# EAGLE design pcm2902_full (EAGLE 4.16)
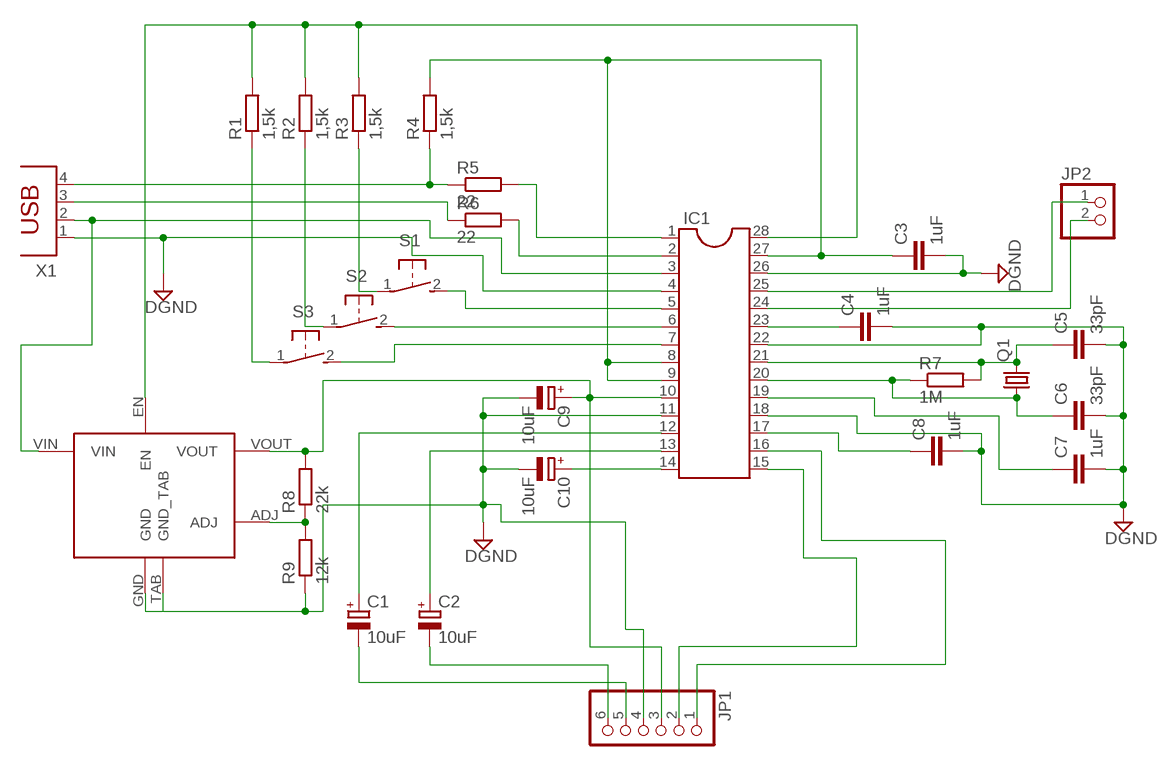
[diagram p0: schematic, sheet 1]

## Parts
C1  10uF  CPOL-EUE2.5-5  [E2,5-5]
C2  10uF  CPOL-EUE2.5-5  [E2,5-5]
C3  1uF  C-EU050-024X044  [C050-024X044]
C4  1uF  C-EU050-024X044  [C050-024X044]
C5  33pF  C-EU050-024X044  [C050-024X044]
C6  33pF  C-EU050-024X044  [C050-024X044]
C7  1uF  C-EU050-024X044  [C050-024X044]
C8  1uF  C-EU050-024X044  [C050-024X044]
C9  10uF  CPOL-EUE2.5-5  [E2,5-5]
C10  10uF  CPOL-EUE2.5-5  [E2,5-5]
IC1  DIL28  [DIL28-6]
JP1  PINHD-1X6  [1X06]
JP2  PINHD-1X2  [1X02]
Q1  CRYTALHC49S  [HC49/S]
R1  1,5k  R-EU_0204/7  [0204/7]
R2  1,5k  R-EU_0204/7  [0204/7]
R3  1,5k  R-EU_0204/7  [0204/7]
R4  1,5k  R-EU_0204/7  [0204/7]
R5  22  R-EU_0204/7  [0204/7]
R6  22  R-EU_0204/7  [0204/7]
R7  1M  R-EU_0204/5  [0204/5]
R8  22k  R-EU_0204/5  [0204/5]
R9  12k  R-EU_0204/5  [0204/5]
S1  31-XX  [B3F-31XX]
S2  31-XX  [B3F-31XX]
S3  31-XX  [B3F-31XX]
U$1  REG102GA-A  [SOT223-5]
X1  PN87520  [PN87520]

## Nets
D_OUT: IC1.25 JP2.1
DGND: C3.2 C4.2 C5.2 C6.2 C7.2 C8.2 C9.- C10.- IC1.4 IC1.11 IC1.18 IC1.22 IC1.26 JP1.4 R9.1 U$1.GND U$1.TAB(GND_TAB) X1.1
N$1: C10.+ IC1.14
N$2: C9.+ IC1.10 JP1.3 R8.2 U$1.VOUT
N$3: IC1.1 R5.2
N$4: R4.1 R5.1 X1.4
N$5: R6.1 X1.3
N$6: IC1.2 R6.2
N$7: IC1.6 S2.2(S)
N$8: C3.1 IC1.8 IC1.9 IC1.27 R4.2
N$9: IC1.7 S3.2(S)
N$10: IC1.5 S1.2(S)
N$11: R1.1 S3.1(P)
N$12: R2.1 S2.1(P)
N$13: R3.1 S1.1(P)
N$14: C4.1 IC1.23
N$15: IC1.28 R1.2 R2.2 R3.2 U$1.EN
N$16: C1.+ IC1.12
N$17: C2.+ IC1.13
N$18: C5.1 IC1.21 Q1.2 R7.2
N$19: C6.1 IC1.20 Q1.1 R7.1
N$20: C7.1 IC1.19
N$21: C8.1 IC1.17
N$22: IC1.16 JP1.1
N$23: IC1.24 JP2.2
N$26: IC1.3 U$1.VIN X1.2
N$27: IC1.15 JP1.2
N$28: C1.- JP1.5
N$29: C2.- JP1.6
N$32: R8.1 R9.2 U$1.ADJ

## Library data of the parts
C1 C2 C9 C10 = rcl:CPOL-EU: POLARIZED CAPACITOR, European symbol
C3-C8 = rcl:C-EU: CAPACITOR, European symbol
IC1 = ic-package:DIL28: Dual In Line
JP1 = pinhead:PINHD-1X6: PIN HEADER
JP2 = pinhead:PINHD-1X2: PIN HEADER
Q1 = crystal:CRYTAL: CRYSTAL
R1-R9 = rcl:R-EU_: RESISTOR, European symbol
S1-S3 = switch-omron:31-XX: OMRON SWITCH
U$1 = Reg102:REG102GA-A
X1 = con-berg:PN87520: BERG USB connector

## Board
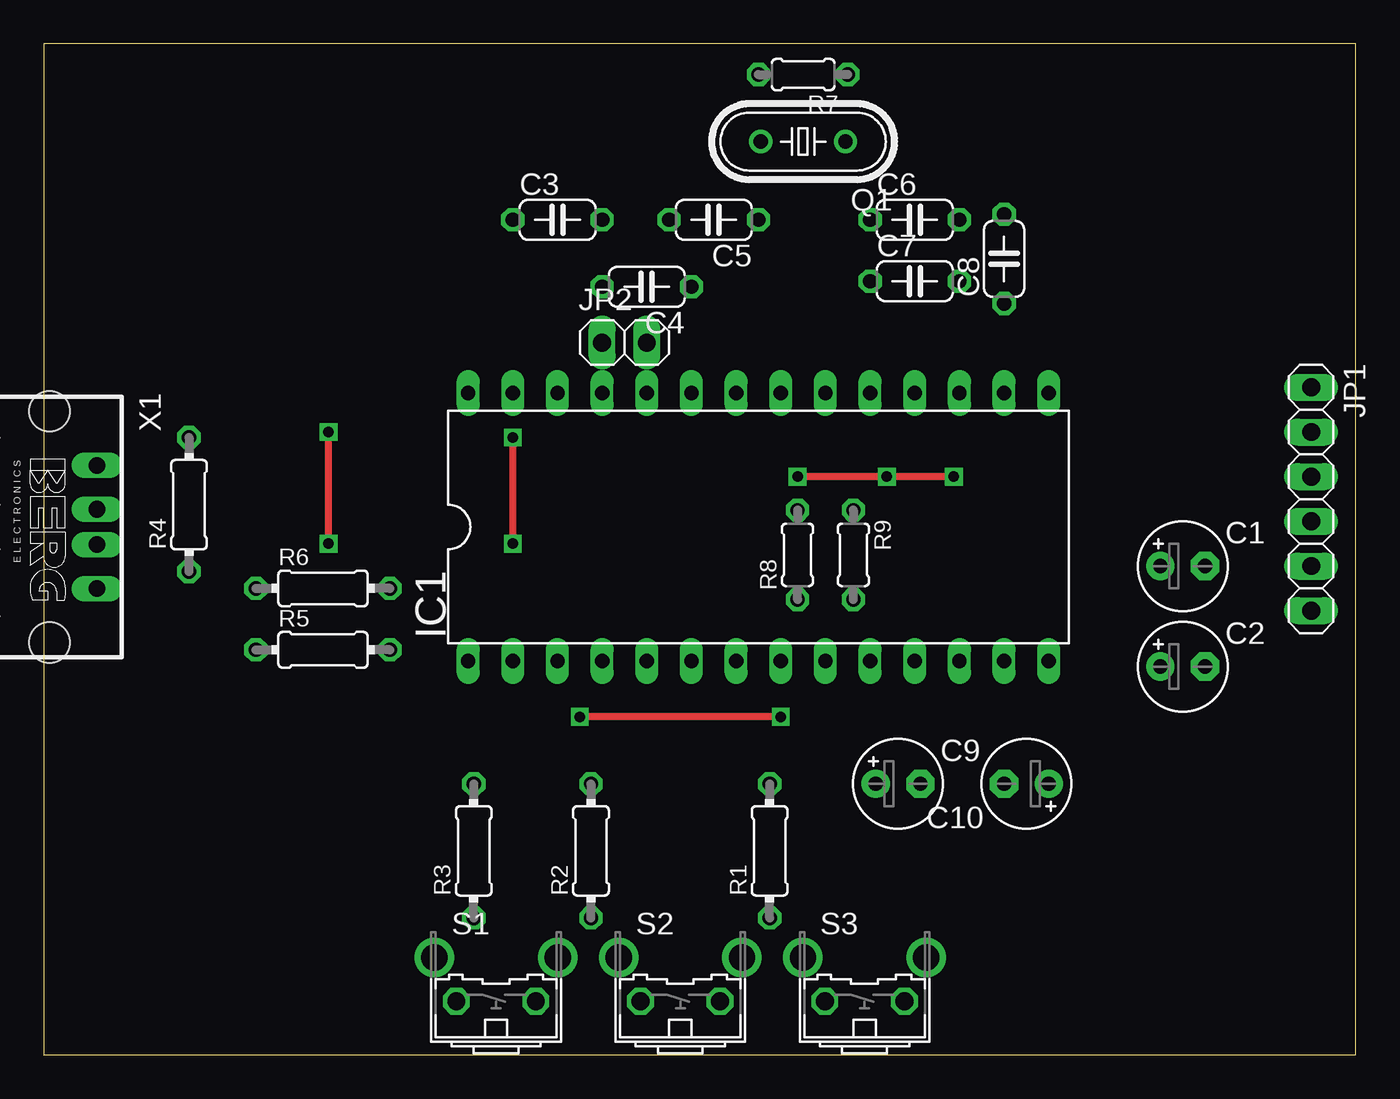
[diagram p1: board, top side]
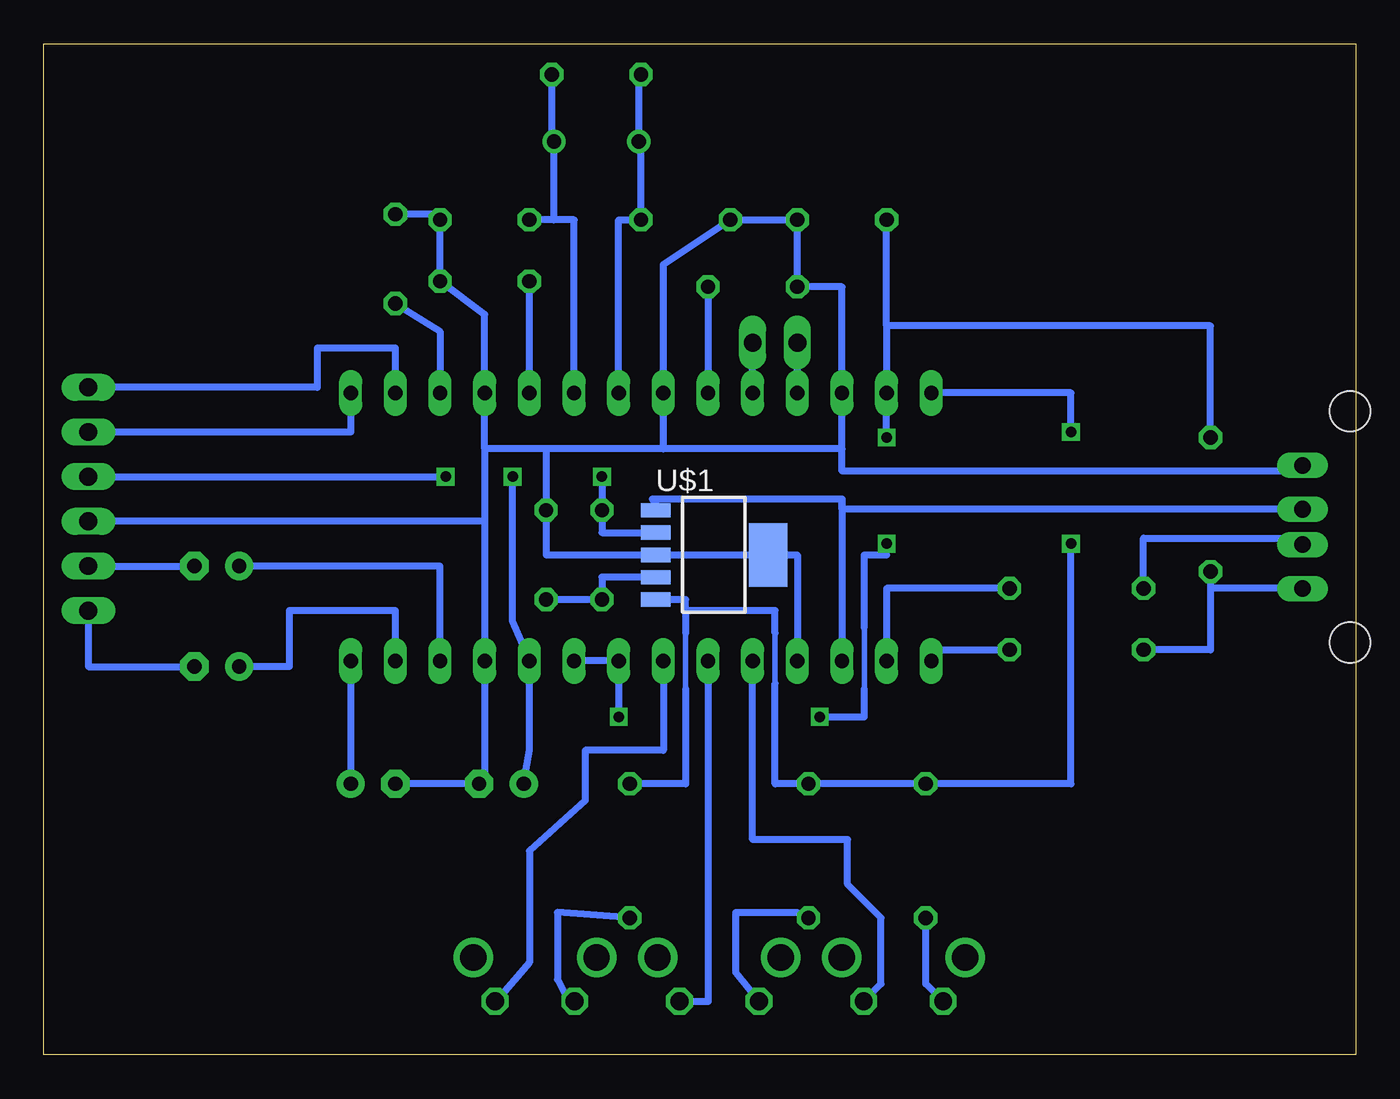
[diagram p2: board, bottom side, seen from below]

Size 74.59 x 57.45 mm. Coordinates in mm from the lower left corner, seen from the top.
Outline: 0,0 74.59,0 74.59,57.45 0,57.45 0,0
Copper layers (1*16): Top 0.035mm / dielectric 1.5mm / Bottom 0.035mm
Design rules "default": minimum track width 10mil, minimum drill 24mil, track to track 8mil, track to pad 8mil, pad to pad 8mil, via to via 8mil, smd to smd 8mil, copper to edge 40mil, drill to drill 8mil, minimum pad ring 10mil, minimum via ring 8mil, stop-mask expansion 4mil, vias tented up to drill 0mil, thermal gap 10mil

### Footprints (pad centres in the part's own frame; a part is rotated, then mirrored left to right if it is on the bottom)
E2,5-5 = drill 0.813 pad 1.6 round: + -1.27,0 | drill 0.813 pad 1.6 octagon: - 1.27,0
C050-024X044 = drill 0.813 octagon: 1 -2.54,0; 2 2.54,0
DIL28-6 = drill 0.813 long: 1 -16.51,-7.62; 2 -13.97,-7.62; 3 -11.43,-7.62; 4 -8.89,-7.62; 5 -6.35,-7.62; 6 -3.81,-7.62; 7 -1.27,-7.62; 8 1.27,-7.62; 9 3.81,-7.62; 10 6.35,-7.62; 11 8.89,-7.62; 12 11.43,-7.62; 13 13.97,-7.62; 14 16.51,-7.62; 15 16.51,7.62; 16 13.97,7.62; 17 11.43,7.62; 18 8.89,7.62; 19 6.35,7.62; 20 3.81,7.62; 21 1.27,7.62; 22 -1.27,7.62; 23 -3.81,7.62; 24 -6.35,7.62; 25 -8.89,7.62; 26 -11.43,7.62; 27 -13.97,7.62; 28 -16.51,7.62
1X06 = drill 1.016 long: 1 -6.35,0; 2 -3.81,0; 3 -1.27,0; 4 1.27,0; 5 3.81,0; 6 6.35,0
1X02 = drill 1.016 long: 1 -1.27,0; 2 1.27,0
HC49/S = drill 0.813 round: 1 -2.413,0; 2 2.413,0
0204/7 = drill 0.813 octagon: 1 -3.81,0; 2 3.81,0
0204/5 = drill 0.813 octagon: 1 -2.54,0; 2 2.54,0
B3F-31XX = drill 1.016 octagon: 1 -2.261,-1.245; 2 2.261,-1.245 | drill 1.499 pad 2.159 round: 3 -3.505,1.245; 4 3.505,1.245
SOT223-5 = smd 0.813 x 1.676: ADJ 1.27,-3.302; EN 2.54,-3.302; GND 0,-3.302; VIN -2.54,-3.302; VOUT -1.27,-3.302 | smd 3.6 x 2.2: TAB 0,3.099
PN87520 = drill 0.95 long: 1 -3.5,2.71; 2 -1,2.71; 3 1,2.71; 4 3.5,2.71 | hole 2.3: -6.57,0; 6.57,0

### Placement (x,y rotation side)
C1  64.77,27.78 0 top
C2  64.77,22.06 0 top
C3  29.21,47.46 0 top
C4  34.29,43.65 180 top
C5  38.1,47.46 180 top
C6  49.52,47.46 0 top
C7  49.52,43.97 0 top
C8  54.6,45.24 90 top
C9  48.57,15.39 0 top
C10  55.88,15.39 180 top
IC1  40.64,30 0 top
JP1  72.07,31.59 270 top
JP2  33.02,40.48 0 top
Q1  43.18,51.91 180 top
R1  41.27,11.58 90 top
R2  31.11,11.58 90 top
R3  24.44,11.58 90 top
R4  8.25,31.27 90 top
R5  15.87,23.01 0 top
R6  15.87,26.5 0 top
R7  43.18,55.72 180 top
R8  42.86,28.41 90 top
R9  46.03,28.41 270 top
S1  25.71,4.28 0 top
S2  36.19,4.28 0 top
S3  46.67,4.28 0 top
U$1  36.51,28.41 270 bottom
X1  0.31,30 270 top

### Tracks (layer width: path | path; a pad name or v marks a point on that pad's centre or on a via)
D_OUT
  Bottom 0.406: IC1.25 JP2.1
DGND
  Bottom 0.406: C8.2 52.07,47.78 C6.2 C7.2 49.52,42.06 IC1.18 49.52,34.44 | X1.1 3.02,33.17 29.21,33.17 29.21,34.44 | 29.21,34.44 IC1.26 29.21,43.65 C4.2 C3.2 C5.2 39.37,44.92 IC1.22 39.37,34.44 | 29.21,34.44 39.37,34.44 | 39.37,34.44 46.03,34.44 | 46.03,34.44 49.52,34.44 | 49.52,34.44 49.52,30.31 | 49.52,30.31 IC1.11 49.52,15.39 C9.- C10.- | 49.52,34.44 49.52,31.27 | 46.03,34.44 R9.1 46.03,28.41 U$1.GND U$1.TAB 31.75,28.41 IC1.4 | 72.38,30.31 JP1.4 49.52,30.31
N$1
  Bottom 0.406: IC1.14 C10.+
N$2  (via drill 0.6)
  Top 0.406: v42.86,32.85 v47.94,32.85 47.94,32.54 48.26,32.85 v51.75,32.85
  Bottom 0.406: U$1.VOUT 42.86,29.68 R8.2 v42.86,32.85 | C9.+ 46.98,17.3 IC1.10 47.94,24.6 v47.94,32.85 | JP1.3 v51.75,32.85
N$3
  Bottom 0.406: IC1.1 24.12,23.01 R5.2
N$4
  Bottom 0.406: X1.4 8.25,26.5 | R4.1 8.25,26.5 | 8.25,26.5 8.25,23.01 R5.1
N$5
  Bottom 0.406: X1.3 3.02,29.36 12.06,29.36 R6.1
N$6
  Bottom 0.406: R6.2 26.66,26.5 IC1.2
N$7
  Bottom 0.406: S2.2 38.45,3.01 36.83,3.01 IC1.6
N$8  (via drill 0.6)
  Top 0.406: v41.91,19.2 v30.48,19.2 | v26.66,29.04 v26.66,35.08
  Bottom 0.305: 27.94,20.79 27.94,24.28
  Bottom 0.406: 26.66,41.43 IC1.27 v26.66,35.08 | 26.66,41.43 C3.1 | R4.2 8.25,41.43 26.66,41.43 | IC1.9 IC1.8 v41.91,19.2 | v30.48,19.2 27.94,19.2 27.94,20.79 | 27.94,24.28 27.94,28.41 26.66,28.41 v26.66,29.04
N$9
  Bottom 0.406: IC1.7 39.37,17.3 43.81,17.3 43.81,14.44 46.98,11.58 46.98,5.23 48.89,3.01 48.93,3.01 S3.2
N$10
  Bottom 0.406: S1.2 26.98,4.03 26.98,7.77 28.89,9.68 28.89,12.22 34.29,12.22 IC1.5
N$11
  Bottom 0.406: R1.1 45.4,8.09 45.4,4.28 44.76,3.01 S3.1
N$12
  Bottom 0.406: S2.1 35.24,4.66 35.24,8.09 31.75,8.09 R2.1
N$13
  Bottom 0.406: S1.1 24.44,4.03 R3.1
N$14
  Bottom 0.406: C4.1 IC1.23
N$15  (via drill 0.6)
  Top 0.406: v16.19,29.04 v16.19,35.39
  Bottom 0.305: 38.1,23.96 38.1,20.79 | 33.02,21.11 33.02,23.96
  Bottom 0.406: 38.1,25.24 38.1,25.87 U$1.EN | 38.1,25.24 38.1,23.96 | 38.1,20.79 38.1,15.39 R1.2 | R3.2 R2.2 33.02,15.39 33.02,21.11 | R3.2 24.12,15.39 | 38.1,25.24 33.02,25.24 33.02,23.96 | IC1.28 16.19,37.62 v16.19,35.39 | v16.19,29.04 16.19,15.39 R3.2
N$16
  Bottom 0.406: IC1.12 52.07,27.78 C1.+
N$17
  Bottom 0.406: IC1.13 54.6,25.24 60.64,25.24 60.64,22.06 C2.+
N$18
  Bottom 0.406: IC1.21 41.91,47.46 C5.1 40.64,51.59 Q1.2 40.76,55.4 R7.2
N$19
  Bottom 0.406: 45.59,47.46 Q1.1 45.72,51.59 R7.1 | 45.59,47.46 C6.1 | 45.59,47.46 44.45,47.46 IC1.20
N$20
  Bottom 0.406: IC1.19 C7.1
N$21
  Bottom 0.406: C8.1 52.07,41.11 IC1.17
N$22
  Bottom 0.406: IC1.16 54.6,40.16 59.05,40.16 59.05,37.93 JP1.1
N$23
  Bottom 0.406: JP2.2 33.97,40.48 34.29,40.16 IC1.24
N$26
  Bottom 0.406: X1.2 29.21,31 29.21,31.59 | 29.21,31.59 IC1.3 | 29.21,31.59 40,31.59 39.81,31.39 U$1.VIN
N$27
  Bottom 0.406: IC1.15 57.15,35.39 JP1.2
N$28
  Bottom 0.406: JP1.5 C1.-
N$29
  Bottom 0.406: JP1.6 72.07,22.06 C2.-
N$32
  Bottom 0.406: R9.2 R8.1 42.86,27.14 U$1.ADJ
